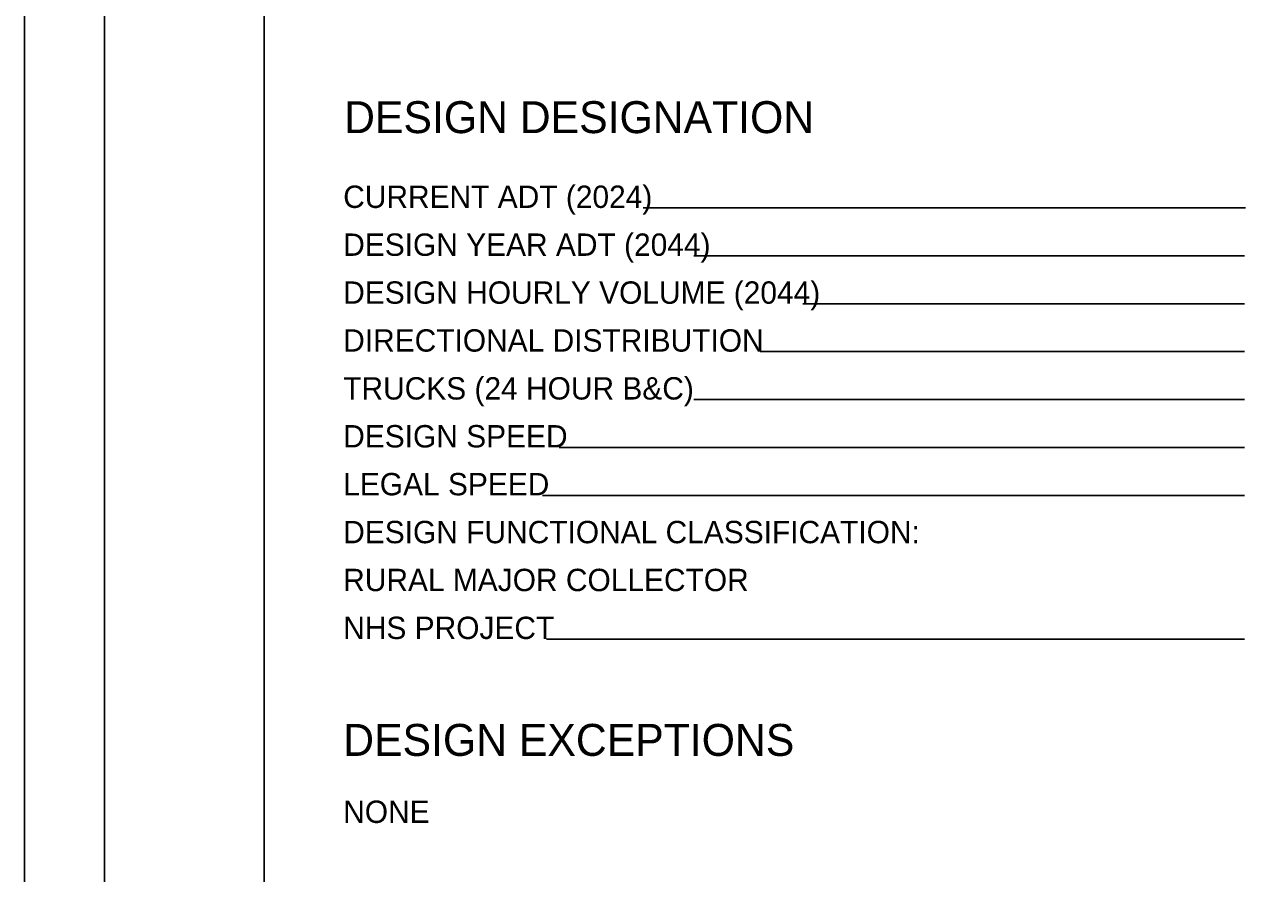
# Model space of a CAD drawing. Extents: x 0 to 34, y 0 to 22.
# Drawn here: x 0 to 7.69, y 5.64 to 10.95 of the extents above; entities that cross this region are included whole.
import ezdxf

# ---------------------------------------------------------------- set-up
doc = ezdxf.new("R2010")
doc.units = 0
for name, color, linetype in [('SH_Border', 7, 'Continuous'), ('SH_Cut_Line', 7, 'Continuous'), ('SH_Data', 7, 'Continuous'), ('SH_Text', 7, 'Continuous')]:
    doc.layers.add(name, color=color, linetype=linetype)

msp = doc.modelspace()

# ---------------------------------------------------------------- linework, layer by layer
at = {"layer": 'SH_Border'}
for points in [[(0.5, 21.5), (1.5, 21.5), (1.5, 0.5), (0.5, 0.5)], [(1.5, 21.5), (33.5, 21.5), (33.5, 0.5), (1.5, 0.5)]]:
    msp.add_lwpolyline(points, close=True, dxfattribs=at)
at = {"layer": 'SH_Cut_Line'}
msp.add_lwpolyline([(0, 0), (34, 0), (34, 22), (0, 22)], close=True, dxfattribs=at)
at = {"layer": 'SH_Data'}
for p, q in [((7.6424, 9.8062), (3.871, 9.8062)), ((7.6368, 9.5062), (4.1885, 9.5062)), ((7.6368, 9.2062), (4.8723, 9.2062)), ((7.6368, 8.9062), (4.6037, 8.9062)), ((7.6368, 8.6062), (4.1885, 8.6062)), ((7.6368, 8.3062), (3.346, 8.3062)), ((7.6368, 8.0062), (3.2422, 8.0062)), ((7.6368, 7.1062), (3.2669, 7.1062))]:
    msp.add_line(p, q, dxfattribs=at)

# ---------------------------------------------------------------- texts
msp.add_text('DESIGN DESIGNATION', height=0.2, dxfattribs=at).set_placement((2, 10.2747))
at = {"layer": 'SH_Text'}
for s, height, p in [('CURRENT ADT (2024)', 0.14, (1.9944, 9.8062)), ('DESIGN YEAR ADT (2044)', 0.14, (1.9944, 9.5062)), ('DESIGN HOURLY VOLUME (2044)', 0.14, (1.9944, 9.2062)), ('DIRECTIONAL DISTRIBUTION', 0.14, (1.9944, 8.9062)), ('TRUCKS (24 HOUR B&C)', 0.14, (1.9944, 8.6062)), ('DESIGN SPEED', 0.14, (1.9944, 8.3062)), ('LEGAL SPEED', 0.14, (1.9944, 8.0062)), ('DESIGN FUNCTIONAL CLASSIFICATION:', 0.14, (1.9944, 7.7062)), ('RURAL MAJOR COLLECTOR', 0.14, (1.9944, 7.4062)), ('NHS PROJECT', 0.14, (1.9944, 7.1062)), ('DESIGN EXCEPTIONS', 0.2, (1.9944, 6.3744)), ('NONE', 0.14, (1.9944, 5.9544))]:
    msp.add_text(s, height=height, dxfattribs=at).set_placement(p)

doc.saveas('drawing.dxf')
